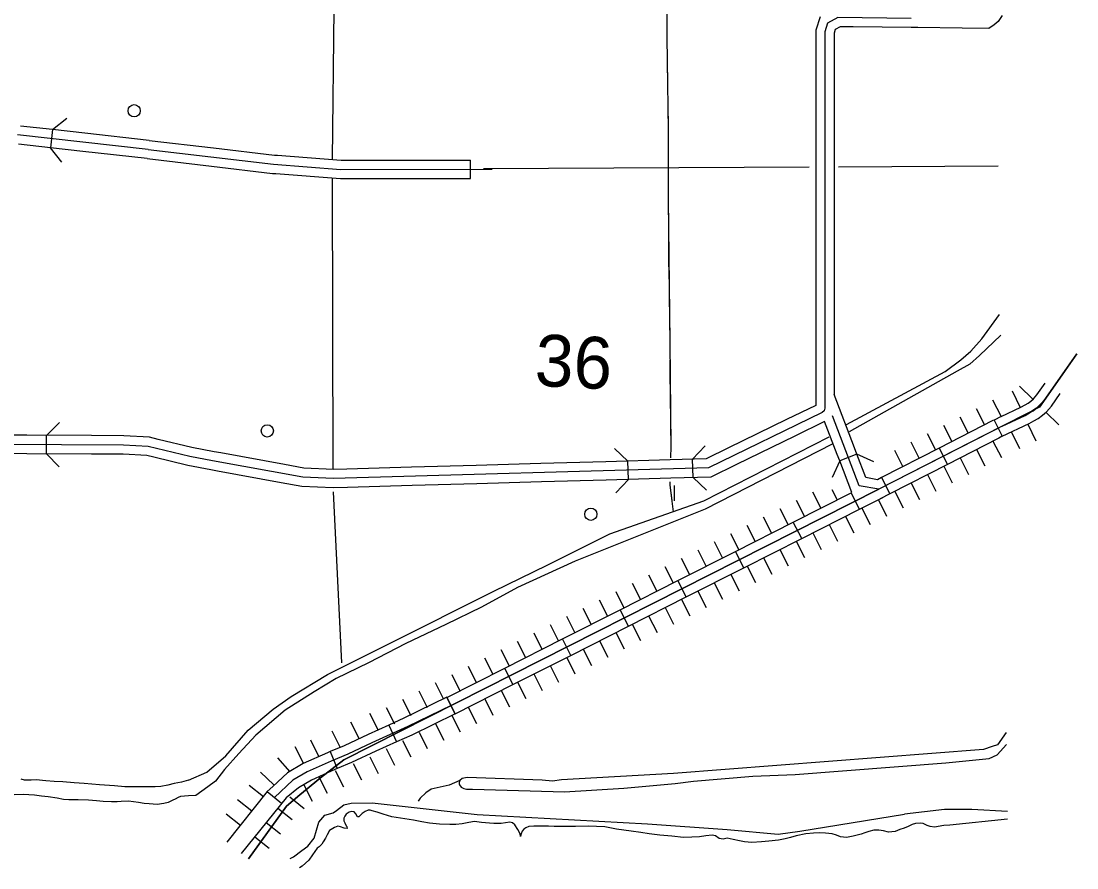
# Model space of a CAD drawing. Extents: x -4306 to 3843, y 131 to 8053.
# Drawn here: x 1003 to 2381, y 131 to 1237 of the extents above; entities that cross this region are included whole.
import ezdxf

# ---------------------------------------------------------------- set-up
doc = ezdxf.new("R2010")
doc.units = 0
for name, color, linetype in [('29', 7, 'Continuous'), ('32', 7, 'Continuous'), ('35', 7, 'Continuous'), ('38', 7, 'Continuous'), ('43', 7, 'Continuous'), ('5', 7, 'Continuous'), ('56', 7, 'Continuous')]:
    doc.layers.add(name, color=color, linetype=linetype)

msp = doc.modelspace()

# ---------------------------------------------------------------- linework, layer by layer
at = {"layer": '29'}
for p, q in [((2381.1, 802.6), (2332.4, 733)), ((2381.1, 802.6), (2332.4, 733)), ((2381.1, 802.6), (2338.4, 741.4)), ((2365.1, 779.6), (2332.4, 733)), ((2306.3, 760.2), (2323.7, 743.1)), ((2296.7, 754.1), (2307, 732.4)), ((2332.4, 733), (2122.4, 625.6)), ((2332.4, 733), (2122.4, 625.6)), ((2332.4, 733), (2122.4, 625.6)), ((2249.7, 731.1), (2260.6, 709.7)), ((2270.8, 742.5), (2282.1, 720.5)), ((2328.6, 731.5), (2313.4, 722.1)), ((2338.4, 741.4), (2328.6, 731.5)), ((2228.3, 720.2), (2239.2, 698.8)), ((2228.3, 720.2), (2239.2, 698.8)), ((2313.4, 722.1), (2283.6, 708)), ((2340.8, 726.2), (2357.6, 709.7)), ((2206.9, 709.3), (2217.9, 687.9)), ((2317.3, 710.7), (2327.6, 689)), ((2185.6, 698.3), (2196.5, 677)), ((2295.7, 700.4), (2306, 678.7)), ((2295.7, 700.4), (2306, 678.7)), ((2142.8, 676.5), (2153.8, 655.1)), ((2164.2, 687.4), (2175.1, 666)), ((2164.2, 687.4), (2175.1, 666)), ((2250.2, 677.4), (2261.1, 656.1)), ((2250.2, 677.4), (2261.1, 656.1)), ((2271.5, 688.4), (2282.5, 667)), ((2228.8, 666.5), (2239.7, 645.1)), ((2207.4, 655.6), (2218.4, 634.2)), ((2186.1, 644.7), (2197, 623.3)), ((2186.1, 644.7), (2197, 623.3)), ((2122.4, 625.6), (1424.2, 272.3)), ((2122.4, 625.6), (1424.2, 272.3)), ((2122.4, 625.6), (1424.2, 272.3)), ((2036, 622.2), (2046.8, 600.8)), ((2036, 622.2), (2046.8, 600.8)), ((2061.2, 625.5), (2068.2, 611.6)), ((2143.3, 622.8), (2154.3, 601.4)), ((2164.7, 633.7), (2175.6, 612.4)), ((2014.6, 611.4), (2025.4, 589.9)), ((2121.9, 611.9), (2132.7, 590.4)), ((2121.9, 611.9), (2132.7, 590.4)), ((1993.1, 600.5), (2004, 579.1)), ((2100.5, 601), (2111.3, 579.6)), ((1971.7, 589.7), (1982.6, 568.3)), ((1971.7, 589.7), (1982.6, 568.3)), ((2057.6, 579.4), (2068.5, 557.9)), ((2057.6, 579.4), (2068.5, 557.9)), ((2079.1, 590.2), (2089.9, 568.8)), ((1928.9, 568), (1939.7, 546.6)), ((1950.3, 578.9), (1961.1, 557.4)), ((2036.2, 568.5), (2047.1, 547.1)), ((1907.5, 557.2), (1918.3, 535.8)), ((1907.5, 557.2), (1918.3, 535.8)), ((2014.8, 557.7), (2025.6, 536.3)), ((1886, 546.3), (1896.9, 524.9)), ((1993.4, 546.9), (2004.2, 525.4)), ((1993.4, 546.9), (2004.2, 525.4)), ((1843.2, 524.7), (1854, 503.3)), ((1843.2, 524.7), (1854, 503.3)), ((1864.6, 535.5), (1875.5, 514.1)), ((1950.6, 525.2), (1961.4, 503.8)), ((1972, 536), (1982.8, 514.6)), ((1821.8, 513.8), (1832.6, 492.4)), ((1929.1, 514.3), (1940, 492.9)), ((1929.1, 514.3), (1940, 492.9)), ((1800.4, 503), (1811.2, 481.6)), ((1907.7, 503.5), (1918.6, 482.1)), ((1779, 492.2), (1789.8, 470.7)), ((1779, 492.2), (1789.8, 470.7)), ((1886.3, 492.7), (1897.1, 471.3)), ((1736.1, 470.5), (1747, 449.1)), ((1757.5, 481.3), (1768.4, 459.9)), ((1843.5, 471), (1854.3, 449.6)), ((1864.9, 481.8), (1875.7, 460.4)), ((1864.9, 481.8), (1875.7, 460.4)), ((1714.7, 459.7), (1725.5, 438.2)), ((1714.7, 459.7), (1725.5, 438.2)), ((1822, 460.2), (1832.9, 438.7)), ((1693.3, 448.8), (1704.1, 427.4)), ((1800.6, 449.3), (1811.5, 427.9)), ((1800.6, 449.3), (1811.5, 427.9)), ((1671.9, 438), (1682.7, 416.6)), ((1757.8, 427.7), (1768.6, 406.2)), ((1779.2, 438.5), (1790.1, 417.1)), ((1629, 416.3), (1639.9, 394.9)), ((1650.5, 427.2), (1661.3, 405.7)), ((1650.5, 427.2), (1661.3, 405.7)), ((1736.4, 416.8), (1747.2, 395.4)), ((1736.4, 416.8), (1747.2, 395.4)), ((1607.6, 405.5), (1618.5, 384.1)), ((1715, 406), (1725.8, 384.6)), ((1586.2, 394.6), (1597, 373.2)), ((1586.2, 394.6), (1597, 373.2)), ((1693.5, 395.2), (1704.4, 373.7)), ((1543.4, 373), (1554.2, 351.6)), ((1564.8, 383.8), (1575.6, 362.4)), ((1650.7, 373.5), (1661.5, 352.1)), ((1672.1, 384.3), (1683, 362.9)), ((1672.1, 384.3), (1683, 362.9)), ((1522, 362.1), (1532.8, 340.7)), ((1522, 362.1), (1532.8, 340.7)), ((1629.3, 362.6), (1640.1, 341.2)), ((1500.5, 351.3), (1511.4, 329.9)), ((1607.9, 351.8), (1618.7, 330.4)), ((1607.9, 351.8), (1618.7, 330.4)), ((1457.5, 333.2), (1468.3, 311.8)), ((1479.1, 340.5), (1490, 319)), ((1586.5, 341), (1597.3, 319.6)), ((1432.9, 321.7), (1443.7, 300.3)), ((1543.6, 319.3), (1554.5, 297.9)), ((1543.6, 319.3), (1554.5, 297.9)), ((1565, 330.1), (1575.9, 308.7)), ((1408.2, 309.9), (1419.1, 288.5)), ((1522.2, 308.5), (1533, 287)), ((1360, 289.6), (1370.9, 268.2)), ((1380.3, 298.5), (1391.1, 277.1)), ((1500.8, 297.6), (1511.6, 276.2)), ((1458, 276), (1468.8, 254.5)), ((1479.4, 286.8), (1490.2, 265.4)), ((1479.4, 286.8), (1490.2, 265.4)), ((1337.6, 274.6), (1353.4, 256.6)), ((1424.2, 272.3), (1393.6, 248.5)), ((1424.2, 272.3), (1393.6, 248.5)), ((1424.2, 272.3), (1393.6, 248.5)), ((1436.3, 267.5), (1447.1, 246.1)), ((1315.2, 256), (1332.8, 239.7)), ((1393.6, 248.5), (1366.5, 226.5)), ((1393.6, 248.5), (1366.5, 226.5)), ((1393.6, 248.5), (1366.5, 226.5)), ((1391.4, 249.9), (1402.2, 228.5)), ((1412.8, 258.4), (1423.6, 236.9)), ((1300.2, 239.2), (1318.9, 224.2)), ((1371.8, 239.7), (1382.7, 218.3)), ((1366.5, 226.5), (1349.3, 211.7)), ((1366.5, 226.5), (1349.3, 211.7)), ((1366.5, 226.5), (1349.3, 211.7)), ((1353.4, 223.8), (1372.2, 208.8)), ((1285.2, 220.5), (1303.9, 205.4)), ((1349.3, 211.7), (1299.7, 142.8)), ((1349.3, 211.7), (1299.7, 142.8)), ((1349.3, 211.7), (1299.7, 142.8)), ((1337.7, 209.1), (1356.4, 194.1)), ((1270.2, 201.7), (1288.9, 186.7)), ((1270.2, 201.7), (1288.9, 186.7)), ((1322.6, 190.4), (1341.4, 175.4)), ((1307.6, 171.7), (1326.3, 156.7)), ((1307.6, 171.7), (1326.3, 156.7))]:
    msp.add_line(p, q, dxfattribs=at)
at = {"layer": '32'}
for p, q in [((2045.8, 1242.6), (2040.1, 1225.2)), ((2283.5, 1244.5), (2278.4, 1236.5)), ((2072.1, 1229.8), (2065.7, 1226.2)), ((2088.9, 1229.6), (2072.1, 1229.8)), ((2164.6, 1228.7), (2088.9, 1229.6)), ((2173.4, 1228.6), (2164.6, 1228.7)), ((2231.2, 1228), (2173.4, 1228.7)), ((2266.2, 1227.6), (2231.2, 1228)), ((2273.1, 1232.3), (2266.2, 1227.6)), ((2278.4, 1236.5), (2273.1, 1232.3)), ((2040.1, 1225.2), (2040.1, 1185.7)), ((2065.7, 1226.2), (2064.1, 1221.4)), ((2064.1, 1221.4), (2064.1, 1185.7)), ((2040.1, 1185.7), (2040.1, 1119.5)), ((2064.1, 1185.7), (2064.1, 1143.5)), ((2064.1, 1143.5), (2064.2, 1143.5)), ((2064.2, 1143.5), (2064.2, 1101.3)), ((2040.1, 1119.5), (2040.2, 1119.5)), ((2040.2, 1119.5), (2040.2, 1101.3)), ((1043.5, 1095.5), (1001.9, 1100.1)), ((1043.5, 1095.5), (1040.8, 1071.6)), ((1085.8, 1090.7), (1043.5, 1095.5)), ((1169.8, 1081.4), (1085.8, 1090.7)), ((2040.2, 1101.3), (2040.2, 1016.8)), ((2064.2, 1101.3), (2064.2, 1016.8)), ((1168.5, 1069.5), (997.9, 1088.4)), ((1040.8, 1071.6), (999.2, 1076.2)), ((1169.9, 1081.4), (1253.8, 1071.5)), ((1083.2, 1066.9), (1040.8, 1071.6)), ((1167.1, 1057.5), (1083.2, 1066.9)), ((1168.5, 1069.5), (1332.2, 1050.3)), ((1253.8, 1071.5), (1333.3, 1062.2)), ((1333.3, 1062.2), (1337.2, 1061.9)), ((1337.2, 1061.9), (1420.6, 1055.5)), ((1167.1, 1057.6), (1251, 1047.7)), ((1251, 1047.7), (1331, 1038.3)), ((1332.2, 1050.3), (1420.1, 1043.5)), ((1420.6, 1055.5), (1505, 1055.6)), ((1420.6, 1055.5), (1420.6, 1055.5)), ((1505, 1055.6), (1589.5, 1055.6)), ((1589.5, 1031.6), (1589.5, 1055.6)), ((1331, 1038.3), (1335.4, 1038)), ((1335.4, 1038), (1419.7, 1031.5)), ((1420.1, 1043.5), (1617.5, 1043.7)), ((1419.7, 1031.5), (1420.6, 1031.5)), ((1420.6, 1031.5), (1505.1, 1031.6)), ((1505.1, 1031.6), (1589.5, 1031.6)), ((2040.2, 1016.8), (2040.1, 932.4)), ((2064.2, 1016.8), (2064.1, 932.4)), ((2040.1, 932.4), (2040.1, 847.9)), ((2064.1, 932.4), (2064.1, 847.9)), ((2040.1, 847.9), (2040.1, 763.4)), ((2064.1, 847.9), (2064.1, 763.4)), ((2338.4, 741.4), (2381.1, 802.6)), ((2040.1, 763.4), (2040.1, 735.2)), ((2064.1, 763.4), (2064.1, 748.9)), ((2328.9, 748.8), (2339.8, 764.4)), ((2090.7, 679.7), (2064.1, 749.2)), ((2324.5, 743.8), (2328.9, 748.8)), ((2347.8, 734), (2359.5, 750.7)), ((2040.1, 735.2), (2002.2, 716.7)), ((2282.1, 720.5), (2307.9, 732.8)), ((2307.9, 732.8), (2313.5, 735.9)), ((2313.5, 735.9), (2317.4, 738)), ((2317.4, 738), (2321, 740.8)), ((2321, 740.8), (2324.5, 743.8)), ((2324, 728), (2328.6, 731.5)), ((2328.6, 731.5), (2333, 735.3)), ((2333, 735.3), (2338.4, 741.4)), ((2341.5, 726.7), (2347.8, 734)), ((2096.8, 630.3), (2061.9, 721.4)), ((2282.1, 720.5), (2273, 716)), ((2283.6, 708), (2313.4, 722.1)), ((2313.4, 722.1), (2319.3, 725.3)), ((2319.3, 725.3), (2324, 728)), ((2325.1, 714.8), (2330.6, 717.9)), ((2330.6, 717.9), (2336.2, 722.2)), ((2336.2, 722.2), (2341.5, 726.7)), ((2002.2, 716.7), (1926.3, 679.6)), ((2051.8, 714.2), (2012.7, 695.1)), ((2068.3, 671.1), (2051.8, 714.2)), ((2281.9, 707.1), (2122.4, 625.6)), ((2271.5, 715.3), (2201.2, 679.4)), ((2273, 716), (2271.5, 715.3)), ((2273, 716), (2283.8, 694.8)), ((2283.8, 694.8), (2318.8, 711.4)), ((2318.8, 711.4), (2325.1, 714.8)), ((1010.2, 696.1), (925.7, 696.5)), ((1094.6, 695.7), (1010.2, 696.1)), ((1035.6, 671.9), (1035.7, 695.9)), ((1136.7, 695.4), (1094.6, 695.7)), ((1170.2, 693.5), (1136.7, 695.4)), ((1181.5, 690.7), (1170.2, 693.5)), ((1225.5, 680.1), (1181.5, 690.7)), ((2012.7, 695.1), (1936.8, 658)), ((2277.3, 691.3), (2212.1, 658)), ((2279.1, 692.3), (2277.3, 691.3)), ((2283.8, 694.8), (2279.1, 692.3)), ((1254.9, 674.6), (1225.5, 680.1)), ((1926.3, 679.6), (1897.1, 665.3)), ((2093.9, 671.4), (2090.7, 679.7)), ((2201.2, 679.4), (2126, 640.9)), ((2201.2, 679.4), (2212.1, 658)), ((1010, 672.1), (925.6, 672.5)), ((1094.5, 671.6), (1010, 672.1)), ((1136, 671.4), (1094.5, 671.6)), ((1166.7, 669.6), (1136, 671.4)), ((1175.9, 667.4), (1166.7, 669.6)), ((1220.5, 656.7), (1175.9, 667.4)), ((1263.4, 673), (1254.9, 674.6)), ((1346.5, 657.8), (1263.4, 673)), ((1850.3, 664), (1765.9, 661.6)), ((1795.6, 638.4), (1794.9, 662.4)), ((1897.1, 665.3), (1850.3, 664)), ((1880, 640.8), (1879.4, 664.8)), ((2071.5, 662.8), (2068.3, 671.1)), ((2093.9, 671.4), (2071.5, 662.8)), ((2087.4, 621.3), (2071.5, 662.8)), ((2105.6, 640.9), (2093.9, 671.4)), ((1250.5, 651), (1220.5, 656.7)), ((1259.1, 649.4), (1250.5, 651)), ((1342.2, 634.2), (1259.1, 649.4)), ((1371.7, 653.2), (1346.5, 657.8)), ((1410.4, 651.5), (1371.7, 653.2)), ((1428.1, 652), (1410.4, 651.5)), ((1512.5, 654.4), (1428.1, 652)), ((1597, 656.8), (1512.5, 654.4)), ((1681.4, 659.2), (1597, 656.8)), ((1765.9, 661.6), (1681.4, 659.2)), ((1936.8, 658), (1903, 641.5)), ((2212.1, 658), (2136.9, 619.5)), ((1369, 629.3), (1342.2, 634.2)), ((1682.1, 635.2), (1597.6, 632.8)), ((1766.6, 637.6), (1682.1, 635.2)), ((1851, 640), (1766.6, 637.6)), ((1903, 641.5), (1851, 640)), ((2120.6, 638.1), (2105.6, 640.9)), ((2126, 640.9), (2120.6, 638.1)), ((2126, 640.9), (2136.9, 619.5)), ((1410.2, 627.5), (1369, 629.3)), ((1428.7, 628), (1410.2, 627.5)), ((1424.2, 272.3), (2122.4, 625.6)), ((1513.2, 630.4), (1428.7, 628)), ((1597.6, 632.8), (1513.2, 630.4)), ((2010.9, 582.6), (2087.4, 621.3)), ((2097.2, 599.4), (2086.3, 620.8)), ((2122.4, 625.6), (2096.8, 630.3)), ((2097.2, 599.4), (2127.9, 614.9)), ((2136.9, 619.5), (2124.3, 613.1)), ((2021.8, 561.2), (2097.2, 599.4)), ((1935.5, 544.5), (2010.9, 582.6)), ((2021.8, 561.2), (2010.9, 582.6)), ((1946.4, 523.1), (2021.8, 561.2)), ((1860.2, 506.3), (1935.5, 544.5)), ((1946.4, 523.1), (1935.5, 544.5)), ((1871, 484.9), (1946.4, 523.1)), ((1784.8, 468.2), (1860.2, 506.3)), ((1871, 484.9), (1860.2, 506.3)), ((1795.6, 446.8), (1871, 484.9)), ((1709.4, 430.1), (1784.8, 468.2)), ((1795.6, 446.8), (1784.8, 468.2)), ((1720.2, 408.6), (1795.6, 446.8)), ((1634, 391.9), (1709.4, 430.1)), ((1720.2, 408.6), (1709.4, 430.1)), ((1644.8, 370.5), (1720.2, 408.6)), ((1558.6, 353.8), (1634, 391.9)), ((1644.8, 370.5), (1634, 391.9)), ((1569.4, 332.4), (1644.8, 370.5)), ((1558.7, 353.9), (1502.5, 326.4)), ((1569.4, 332.4), (1558.6, 353.8)), ((1558.7, 353.9), (1569.3, 332.3)), ((1564, 343.1), (1507.6, 315.5)), ((1569.3, 332.3), (1512.7, 304.6)), ((1482.9, 317.6), (1455.6, 305.3)), ((1502.5, 326.4), (1482.9, 317.6)), ((1482.9, 317.6), (1492.7, 295.7)), ((1455.6, 305.3), (1424.4, 290.6)), ((1507.6, 315.5), (1460.6, 294.4)), ((1512.7, 304.6), (1492.7, 295.7)), ((1424.4, 290.6), (1406.1, 282.9)), ((1460.6, 294.4), (1429.3, 279.7)), ((1492.7, 295.7), (1465.6, 283.5)), ((1402.7, 281.4), (1370.8, 267.2)), ((1406.1, 282.9), (1402.7, 281.4)), ((1406.1, 282.9), (1415.5, 260.8)), ((1429.3, 279.7), (1407.5, 270.4)), ((1465.6, 283.5), (1434.2, 268.7)), ((1370.8, 267.2), (1350.3, 255.2)), ((1407.5, 270.4), (1376.2, 256.5)), ((1393.6, 248.5), (1424.2, 272.3)), ((1434.2, 268.7), (1415.5, 260.8)), ((1350.3, 255.2), (1331.1, 237.3)), ((1376.2, 256.5), (1357.5, 245.5)), ((1366.5, 226.5), (1393.6, 248.5)), ((1412.2, 259.4), (1381.7, 245.8)), ((1415.5, 260.8), (1412.2, 259.4)), ((1331.1, 237.3), (1324.1, 230.6)), ((1357.5, 245.5), (1333.5, 223.1)), ((1364.7, 235.8), (1348.5, 222.7)), ((1381.7, 245.8), (1364.7, 235.8)), ((1323.7, 230.9), (1271.2, 164.7)), ((1348.5, 222.7), (1289.9, 149.7)), ((1324.1, 230.6), (1342.8, 215.6)), ((1349.3, 211.7), (1366.5, 226.5)), ((1299.7, 142.8), (1349.3, 211.7))]:
    msp.add_line(p, q, dxfattribs=at)
for points in [[(2164.7, 1240.7), (2069, 1241.8), (2055.7, 1234.4), (2052.1, 1223.3), (2052.1, 1131.5)], [(2052.2, 1131.5), (2052.1, 731.6), (2051.2, 728.2), (2048.7, 726.1), (1900.1, 653.4), (1410.3, 639.5), (1370.3, 641.2), (1252.7, 662.8), (1223, 668.4), (1168.4, 681.6), (1136.3, 683.4), (569.9, 686.2), (-271.6, 689.6)]]:
    msp.add_lwpolyline(points, dxfattribs=at)
at = {"layer": '35'}
msp.add_line((1855.1, 630.6), (1855.4, 610.5), dxfattribs=at)
at = {"layer": '38'}
for p, q in [((2071.5, 662.8), (2061.8, 640.9)), ((2115.9, 661.6), (2093.9, 671.4))]:
    msp.add_line(p, q, dxfattribs=at)
for points in [[(1043.5, 1095.5), (1062.2, 1110.4)], [(1055.8, 1052.9), (1040.8, 1071.6)], [(1035.7, 695.9), (1052.8, 712.8)], [(1777.5, 678.9), (1794.9, 662.4)], [(1879.4, 664.8), (1895.9, 682.3)], [(1052.5, 654.9), (1035.6, 671.9)], [(1795.6, 638.4), (1779.1, 621)], [(1897.5, 624.4), (1880.1, 640.8)]]:
    msp.add_lwpolyline(points, dxfattribs=at)
at = {"layer": '43'}
for points in [[(1844.6, 1438.5), (1845.3, 1319.7), (1845.8, 1216.3), (1847.4, 1094.1), (1847.3, 1005.2), (1849.5, 818.3), (1850.8, 681.6), (1850.5, 666.5)], [(1845.8, 1216.7), (1845.8, 1216.3), (1846.7, 1153.3)], [(1846.9, 1132.2), (1847.4, 1094.1), (1847.4, 1068.8)], [(1847.3, 1047.7), (1847.3, 1005.2), (1847.5, 984.3)], [(1847.8, 963.2), (1848.1, 931.5)], [(1848.1, 931.5), (1848.5, 899.9)], [(1848.8, 878.7), (1849.5, 818.3), (1849.6, 815.4)], [(2080.4, 710), (2209.1, 779.6), (2229.5, 794.6), (2242.6, 805.9), (2257.1, 822.3), (2280.2, 854)], [(2282, 826.8), (2254.1, 800.3), (2241.2, 789), (2224.9, 779.7), (2083.9, 700.8)], [(1849.7, 794.3), (1850.3, 730.9)], [(1850.5, 709.8), (1850.8, 681.6), (1850.5, 666.5)], [(1221.1, 245.6), (1245.2, 256.2), (1269.8, 277.5), (1299.1, 310.8), (1331.7, 338.2), (1355.4, 355.1), (1402.5, 383.6), (1483.7, 424), (1619.8, 492.6), (1689.7, 526.6), (1771.4, 567.3), (1893.9, 610.3), (2057.6, 694.2)], [(2061.7, 684.4), (1895.6, 599.5), (1726, 531.8), (1650.8, 497.2), (1603.9, 471.8), (1557, 449.1), (1504.8, 424.3), (1456.1, 399), (1414.2, 378.6), (1385.2, 361.1), (1347.5, 337), (1309, 304.6), (1286.7, 280.6), (1268.1, 259.5), (1256.3, 244.5), (1246.3, 236.9), (1230.7, 225.6)], [(1849.8, 635.2), (1849.7, 630.8), (1852.1, 611)], [(1849.8, 635.2), (1849.7, 630.8), (1853.9, 596.2)], [(2289, 307.7), (2277.7, 291.8), (2270.6, 289.7), (2259.3, 285.8), (1854.4, 254.3)], [(1585.1, 249.1), (1578.4, 247.8), (1575.5, 245.3), (1574.8, 242.7), (1574.5, 240.5), (1575.1, 239.5), (1577, 236.3), (1580.5, 234.6), (1584, 233.7), (1587.9, 234), (1592, 233.9), (1697.2, 231), (1712, 230.2), (1789.4, 235.1), (1856.6, 241.4), (1880.6, 244.5), (1958.1, 250.7), (2013.4, 253.2), (2209.9, 268.2), (2266.8, 274), (2276.9, 278.7), (2289.2, 292.3)], [(1854.4, 254.3), (1708.2, 246), (1696.4, 244.4), (1682.9, 245.8), (1585.1, 249.1)], [(1221.1, 245.6), (1212, 242.8), (1202.6, 241.1), (1194.3, 238.9), (1185.2, 237.2), (1177.8, 237), (1159, 236.9), (1138, 237), (1124.7, 238), (1104.9, 239.4), (1084.9, 241.1), (1071.8, 242.2), (1057.2, 243.6), (1045.7, 244), (1035, 244.8), (1022.2, 245.9), (1015.7, 245.7), (1006.9, 245.6), (1002.7, 246.8), (1002.7, 246.9)], [(1575.5, 245.3), (1561.4, 239.3), (1538, 234), (1530.9, 228.9), (1523.8, 222.2), (1521.1, 218.3)], [(1230.7, 225.6), (1221.2, 225.2), (1216.1, 224.7), (1210.6, 224.2), (1207.6, 223.1), (1203.6, 221), (1200.6, 219.4), (1194.5, 216.5), (1189.1, 215), (1180.4, 213.9), (1169.9, 214.7), (1163.5, 215.3), (1156.1, 216.4), (1143, 218.3), (1133.3, 217.8), (1128.2, 217.5), (1120.5, 217.3), (1109.9, 217.9), (1101.1, 218.7), (1090.7, 219.5), (1077.3, 219.9), (1065, 220), (1058, 220.5), (1049.5, 222.1), (1038, 224), (1029.3, 224.8), (1020, 225.9), (1005.2, 226.9), (993.7, 226.4)], [(1354.1, 143.4), (1358.3, 145.4), (1369.3, 153.7), (1377.1, 159.5), (1385.1, 169.8), (1391.2, 190.8), (1399.1, 199.8), (1409.9, 203), (1414.4, 205.9), (1424.2, 213.6), (1433.6, 215.6), (1461.2, 216.2), (1598, 200.7), (1820.6, 188.6), (1924.6, 181), (1991.2, 175.2), (2019.5, 178.8), (2156, 201.2)], [(2290.4, 204.9), (2244, 207.3), (2208.1, 207.3), (2156, 201.2)], [(1443.8, 197.9), (1441.7, 197.6), (1439.8, 201.8), (1437.4, 204.3), (1434.2, 204.8), (1430.8, 203.7), (1427, 201.1), (1425.1, 198.8), (1424, 196.1), (1424.1, 192.4), (1425.3, 190), (1425.7, 188.7), (1427.5, 185.7), (1427.8, 184.9), (1428.3, 182.5), (1424.5, 183.1), (1419.5, 184.5), (1416, 185.5), (1411.7, 183.9), (1405.1, 179.7), (1402.4, 174.2), (1400.1, 169.7), (1397.2, 164.9), (1395.1, 162), (1391.8, 158.7), (1389.1, 156.7), (1383.2, 148.2), (1378.1, 141.1), (1373.9, 137.3), (1369.8, 133.1), (1366.1, 131)], [(2290.5, 194.7), (2215.3, 187), (2207.2, 186.2), (2195.2, 184.4), (2189.4, 185.2), (2185.6, 186.5), (2180.6, 188.9), (2176.3, 189.6), (2170.4, 189.2), (2165.9, 187.7), (2161, 185), (2155.5, 182.9), (2150.1, 181.1), (2144, 178.7), (2135.1, 177.7), (2128.8, 179.4), (2122.4, 180.5), (2116.1, 180.2), (2109.3, 178.4), (2104.1, 176.6), (2099.3, 174.9), (2089.2, 172.3), (2080.4, 170.8), (2072.7, 171.6), (2067.1, 173.7), (2061.7, 175.4), (2053.1, 176.5), (2045.6, 176.8), (2037.2, 176.3), (2027.2, 175.5), (2014.7, 172.7), (2007.2, 170.8), (2000.2, 168.9), (1991.5, 167.4), (1978.9, 166.1), (1969.5, 165.1), (1956.9, 164.4), (1947.1, 165.2), (1940.7, 166.2), (1932.4, 168.1), (1924.7, 169.8), (1919.4, 168.7), (1914.1, 169.3), (1909.3, 172.8), (1905, 173.8), (1896.7, 172.9), (1888.4, 171.6), (1878.5, 171), (1867.3, 170.9), (1852.4, 172.4), (1836.4, 173.9), (1822.5, 175.7), (1812, 177.4), (1799.2, 179.1), (1780, 181.6), (1764.6, 184.8), (1743.2, 185.7), (1726.4, 184.9), (1711.8, 184.9), (1698.7, 185.3), (1691.1, 185.6), (1672.2, 185.6), (1665.5, 184.9), (1661.8, 183.3), (1658.9, 181.5), (1657, 179.1), (1655.6, 175.6), (1654.6, 172), (1654.3, 175.3), (1651.4, 181.2), (1647.4, 187.1), (1644.4, 190), (1640.7, 190.9), (1629.6, 189.1), (1619.7, 189.1), (1614, 189.3), (1603.7, 190.5), (1594.8, 191.8), (1587, 190.3), (1578.5, 188.7), (1570.2, 187.9), (1562.2, 187.5), (1548.7, 188.3), (1536, 189.6), (1525.7, 191.3), (1514.8, 193.2), (1486.7, 197.9), (1475.3, 201.4), (1467.5, 203.7), (1461.1, 205.6), (1458.5, 206.4), (1455.8, 206.5), (1451.8, 204.6), (1448, 202), (1445.3, 199.5), (1443.8, 198.3)]]:
    msp.add_lwpolyline(points, dxfattribs=at)
at = {"layer": '5'}
for p, q in [((1409.1, 1056.4), (1411.3, 1253)), ((2069.8, 1047), (2278.5, 1048.1)), ((1606.3, 1044.5), (2031.5, 1046.8)), ((1410, 651.5), (1409, 1032.3)), ((1421.2, 398.9), (1410.3, 622.4))]:
    msp.add_line(p, q, dxfattribs=at)
at = {"layer": '56'}
for centre in [(1150.2, 1120.1), (1324.1, 701.8), (1746.5, 592.9)]:
    msp.add_circle(centre, 8, dxfattribs=at)

# ---------------------------------------------------------------- texts
at = {"layer": '5'}
msp.add_text('36', height=67.59, rotation=357.2006, dxfattribs=at).set_placement((1672.4, 760.9))

doc.saveas('drawing.dxf')
